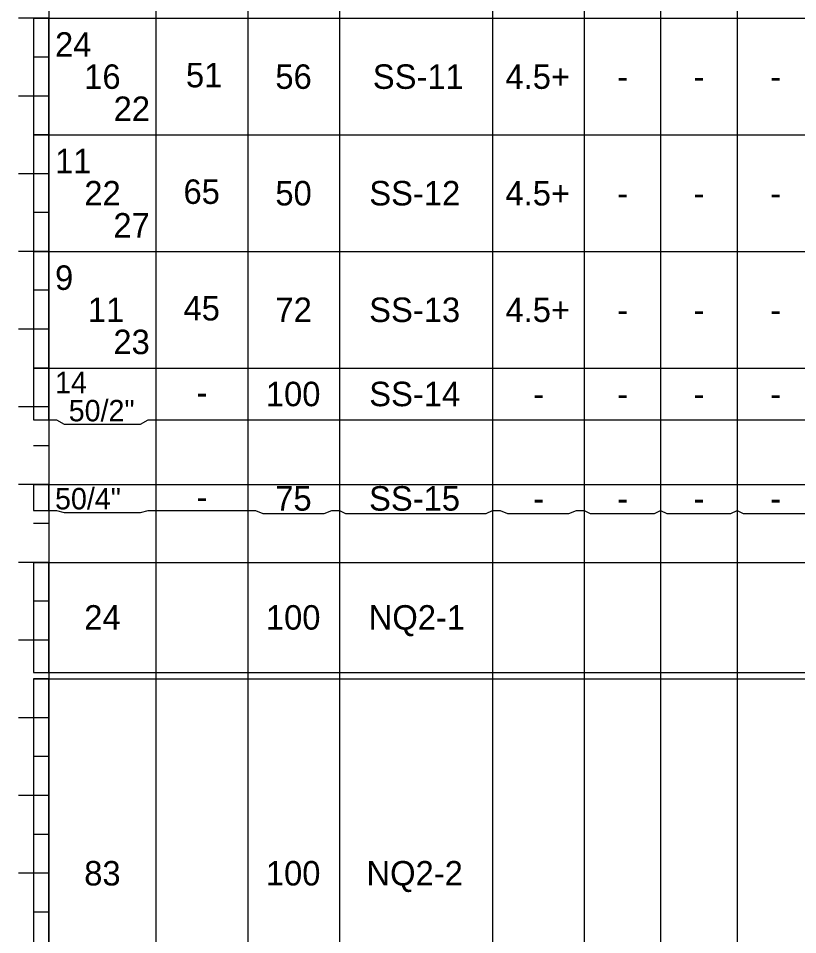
# Model space of a CAD drawing. Extents: x 0 to 0.833, y -0.32 to 0.608.
# Drawn here: x 0.4042 to 0.6165, y -0.0591 to 0.1905 of the extents above; entities that cross this region are included whole.
import ezdxf

# ---------------------------------------------------------------- set-up
doc = ezdxf.new("R2010")
doc.units = 0

msp = doc.modelspace()

# ---------------------------------------------------------------- linework, layer by layer
for points in [[(0.4125, 0.55417), (0.4125, -0.27517)], [(0.4125, 0.55417), (0.4125, -0.27517)], [(0.44167, 0.55417), (0.44167, -0.27517)], [(0.46667, 0.55417), (0.46667, -0.27517)], [(0.49167, 0.55417), (0.49167, -0.27517)], [(0.53333, 0.55417), (0.53333, -0.27517)], [(0.55833, 0.55417), (0.55833, -0.27517)], [(0.57917, 0.54167), (0.57917, -0.27517)], [(0.6, 0.54167), (0.6, -0.27517)], [(0.4125, 0.1905), (0.40417, 0.1905)], [(0.40833, 0.1905), (0.40833, 0.15875)], [(0.40833, 0.1905), (0.4125, 0.1905)], [(0.4125, 0.1905), (0.44167, 0.1905)], [(0.44167, 0.1905), (0.46667, 0.1905)], [(0.46667, 0.1905), (0.49167, 0.1905)], [(0.49167, 0.1905), (0.53333, 0.1905)], [(0.53333, 0.1905), (0.55833, 0.1905)], [(0.55833, 0.1905), (0.57917, 0.1905)], [(0.57917, 0.1905), (0.6, 0.1905)], [(0.6, 0.1905), (0.62083, 0.1905)], [(0.4125, 0.17992), (0.40833, 0.17992)], [(0.4125, 0.16933), (0.40417, 0.16933)], [(0.4125, 0.16933), (0.40833, 0.16933)], [(0.40833, 0.15875), (0.4125, 0.15875)], [(0.40833, 0.15875), (0.40833, 0.127)], [(0.40833, 0.15875), (0.4125, 0.15875)], [(0.4125, 0.15875), (0.40833, 0.15875)], [(0.4125, 0.15875), (0.44167, 0.15875)], [(0.44167, 0.15875), (0.46667, 0.15875)], [(0.46667, 0.15875), (0.49167, 0.15875)], [(0.49167, 0.15875), (0.53333, 0.15875)], [(0.53333, 0.15875), (0.55833, 0.15875)], [(0.55833, 0.15875), (0.57917, 0.15875)], [(0.57917, 0.15875), (0.6, 0.15875)], [(0.6, 0.15875), (0.62083, 0.15875)], [(0.4125, 0.14817), (0.40417, 0.14817)], [(0.4125, 0.14817), (0.40833, 0.14817)], [(0.4125, 0.13758), (0.40833, 0.13758)], [(0.4125, 0.127), (0.40417, 0.127)], [(0.40833, 0.127), (0.4125, 0.127)], [(0.40833, 0.127), (0.40833, 0.09525)], [(0.40833, 0.127), (0.4125, 0.127)], [(0.4125, 0.127), (0.40833, 0.127)], [(0.4125, 0.127), (0.44167, 0.127)], [(0.44167, 0.127), (0.46667, 0.127)], [(0.46667, 0.127), (0.49167, 0.127)], [(0.49167, 0.127), (0.53333, 0.127)], [(0.53333, 0.127), (0.55833, 0.127)], [(0.55833, 0.127), (0.57917, 0.127)], [(0.57917, 0.127), (0.6, 0.127)], [(0.6, 0.127), (0.62083, 0.127)], [(0.4125, 0.11642), (0.40833, 0.11642)], [(0.4125, 0.10583), (0.40417, 0.10583)], [(0.4125, 0.10583), (0.40833, 0.10583)], [(0.40833, 0.09525), (0.4125, 0.09525)], [(0.40833, 0.09525), (0.40833, 0.08114)], [(0.40833, 0.09525), (0.4125, 0.09525)], [(0.4125, 0.09525), (0.40833, 0.09525)], [(0.4125, 0.09525), (0.44167, 0.09525)], [(0.44167, 0.09525), (0.46667, 0.09525)], [(0.46667, 0.09525), (0.49167, 0.09525)], [(0.49167, 0.09525), (0.53333, 0.09525)], [(0.53333, 0.09525), (0.55833, 0.09525)], [(0.55833, 0.09525), (0.57917, 0.09525)], [(0.57917, 0.09525), (0.6, 0.09525)], [(0.6, 0.09525), (0.62083, 0.09525)], [(0.4125, 0.08467), (0.40417, 0.08467)], [(0.4125, 0.08467), (0.40833, 0.08467)], [(0.40833, 0.08114), (0.4125, 0.08114)], [(0.4125, 0.08114), (0.41458, 0.08114), (0.41667, 0.07994), (0.4375, 0.07994), (0.43958, 0.08114), (0.44167, 0.08114)], [(0.44167, 0.08114), (0.46667, 0.08114)], [(0.46667, 0.08114), (0.49167, 0.08114)], [(0.49167, 0.08114), (0.53333, 0.08114)], [(0.53333, 0.08114), (0.55833, 0.08114)], [(0.55833, 0.08114), (0.57917, 0.08114)], [(0.57917, 0.08114), (0.6, 0.08114)], [(0.6, 0.08114), (0.62083, 0.08114)], [(0.4125, 0.07408), (0.40833, 0.07408)], [(0.4125, 0.0635), (0.40417, 0.0635)], [(0.40833, 0.0635), (0.40833, 0.05644)], [(0.40833, 0.0635), (0.4125, 0.0635)], [(0.4125, 0.0635), (0.40833, 0.0635)], [(0.4125, 0.0635), (0.44167, 0.0635)], [(0.44167, 0.0635), (0.46667, 0.0635)], [(0.46667, 0.0635), (0.49167, 0.0635)], [(0.49167, 0.0635), (0.53333, 0.0635)], [(0.53333, 0.0635), (0.55833, 0.0635)], [(0.55833, 0.0635), (0.57917, 0.0635)], [(0.57917, 0.0635), (0.6, 0.0635)], [(0.6, 0.0635), (0.62083, 0.0635)], [(0.40833, 0.05644), (0.4125, 0.05644)], [(0.4125, 0.05644), (0.41458, 0.05644), (0.41667, 0.05595), (0.4375, 0.05595), (0.43958, 0.05644), (0.44167, 0.05644)], [(0.44167, 0.05644), (0.46667, 0.05644)], [(0.46667, 0.05644), (0.46875, 0.05644), (0.47083, 0.05562), (0.4875, 0.05562), (0.48958, 0.05644), (0.49167, 0.05644)], [(0.49167, 0.05644), (0.49333, 0.05562), (0.53167, 0.05562), (0.53333, 0.05644)], [(0.53333, 0.05644), (0.53542, 0.05644), (0.5375, 0.05562), (0.55417, 0.05562), (0.55625, 0.05644), (0.55833, 0.05644)], [(0.55833, 0.05644), (0.56, 0.05562), (0.5775, 0.05562), (0.57917, 0.05644)], [(0.57917, 0.05644), (0.58083, 0.05562), (0.59833, 0.05562), (0.6, 0.05644)], [(0.6, 0.05644), (0.60167, 0.05562), (0.61917, 0.05562), (0.62083, 0.05644)], [(0.4125, 0.05292), (0.40833, 0.05292)], [(0.4125, 0.04233), (0.40417, 0.04233)], [(0.40833, 0.04233), (0.40833, 0.01235)], [(0.40833, 0.04233), (0.4125, 0.04233)], [(0.4125, 0.04233), (0.40833, 0.04233)], [(0.4125, 0.04233), (0.44167, 0.04233)], [(0.44167, 0.04233), (0.46667, 0.04233)], [(0.46667, 0.04233), (0.49167, 0.04233)], [(0.49167, 0.04233), (0.53333, 0.04233)], [(0.53333, 0.04233), (0.55833, 0.04233)], [(0.55833, 0.04233), (0.57917, 0.04233)], [(0.57917, 0.04233), (0.6, 0.04233)], [(0.6, 0.04233), (0.62083, 0.04233)], [(0.4125, 0.03175), (0.40833, 0.03175)], [(0.4125, 0.02117), (0.40417, 0.02117)], [(0.4125, 0.02117), (0.40833, 0.02117)], [(0.40833, 0.01235), (0.4125, 0.01235)], [(0.40833, 0.01058), (0.40833, -0.09525)], [(0.40833, 0.01058), (0.4125, 0.01058)], [(0.4125, 0.01058), (0.40833, 0.01058)], [(0.4125, 0.01235), (0.44167, 0.01235)], [(0.4125, 0.01058), (0.44167, 0.01058)], [(0.44167, 0.01235), (0.46667, 0.01235)], [(0.44167, 0.01058), (0.46667, 0.01058)], [(0.46667, 0.01235), (0.49167, 0.01235)], [(0.46667, 0.01058), (0.49167, 0.01058)], [(0.49167, 0.01235), (0.53333, 0.01235)], [(0.49167, 0.01058), (0.53333, 0.01058)], [(0.53333, 0.01235), (0.55833, 0.01235)], [(0.53333, 0.01058), (0.55833, 0.01058)], [(0.55833, 0.01235), (0.57917, 0.01235)], [(0.55833, 0.01058), (0.57917, 0.01058)], [(0.57917, 0.01235), (0.6, 0.01235)], [(0.57917, 0.01058), (0.6, 0.01058)], [(0.6, 0.01235), (0.62083, 0.01235)], [(0.6, 0.01058), (0.62083, 0.01058)], [(0.4125, 0), (0.40417, 0)], [(0.4125, 0), (0.40833, 0)], [(0.4125, -0.01058), (0.40833, -0.01058)], [(0.4125, -0.02117), (0.40417, -0.02117)], [(0.4125, -0.02117), (0.40833, -0.02117)], [(0.4125, -0.03175), (0.40833, -0.03175)], [(0.4125, -0.04233), (0.40417, -0.04233)], [(0.4125, -0.04233), (0.40833, -0.04233)], [(0.4125, -0.05292), (0.40833, -0.05292)]]:
    msp.add_lwpolyline(points)
for points in [[(0.40833, 0.15875), (0.4125, 0.15875), (0.4125, 0.1905), (0.40833, 0.1905)], [(0.40833, 0.127), (0.4125, 0.127), (0.4125, 0.15875), (0.40833, 0.15875)], [(0.40833, 0.09525), (0.4125, 0.09525), (0.4125, 0.127), (0.40833, 0.127)], [(0.40833, 0.08114), (0.4125, 0.08114), (0.4125, 0.09525), (0.40833, 0.09525)], [(0.40833, 0.05644), (0.4125, 0.05644), (0.4125, 0.0635), (0.40833, 0.0635)], [(0.40833, 0.01235), (0.4125, 0.01235), (0.4125, 0.04233), (0.40833, 0.04233)], [(0.40833, -0.09525), (0.4125, -0.09525), (0.4125, 0.01058), (0.40833, 0.01058)]]:
    msp.add_lwpolyline(points, close=True)

# ---------------------------------------------------------------- texts
for s, height, p in [('24', 0.006667, (0.41417, 0.18004)), ('16', 0.006667, (0.42212, 0.17129)), ('51', 0.006667, (0.44984, 0.17171)), ('56', 0.006667, (0.4742, 0.17129)), ('SS-11', 0.006667, (0.50076, 0.17129)), ('4.5+', 0.006667, (0.5369, 0.17129)), ('-', 0.00667, (0.56734, 0.17129)), ('-', 0.00667, (0.58818, 0.17129)), ('-', 0.00667, (0.60901, 0.17129)), ('22', 0.006667, (0.43014, 0.16254)), ('11', 0.006667, (0.41417, 0.14829)), ('22', 0.006667, (0.42215, 0.13954)), ('65', 0.006667, (0.44917, 0.13996)), ('50', 0.006667, (0.47421, 0.13954)), ('SS-12', 0.006667, (0.4998, 0.13954)), ('4.5+', 0.006667, (0.5369, 0.13954)), ('-', 0.00667, (0.56734, 0.13954)), ('-', 0.00667, (0.58818, 0.13954)), ('-', 0.00667, (0.60901, 0.13954)), ('27', 0.006667, (0.43007, 0.13079)), ('9', 0.00667, (0.41417, 0.11654)), ('45', 0.006667, (0.44917, 0.10821)), ('11', 0.006667, (0.42311, 0.10779)), ('72', 0.006667, (0.47423, 0.10779)), ('SS-13', 0.006667, (0.49977, 0.10779)), ('4.5+', 0.006667, (0.5369, 0.10779)), ('-', 0.00667, (0.56734, 0.10779)), ('-', 0.00667, (0.58818, 0.10779)), ('-', 0.00667, (0.60901, 0.10779)), ('23', 0.006667, (0.43007, 0.09904)), ('14', 0.005833, (0.41417, 0.0884)), ('100', 0.006667, (0.47162, 0.08486)), ('SS-14', 0.006667, (0.49978, 0.08486)), ('-', 0.00667, (0.45276, 0.08528)), ('-', 0.00667, (0.54443, 0.08486)), ('-', 0.00667, (0.56734, 0.08486)), ('-', 0.00667, (0.58818, 0.08486)), ('-', 0.00667, (0.60901, 0.08486)), ('50/2"', 0.005833, (0.4179, 0.08074)), ('50/4"', 0.005833, (0.41417, 0.05676)), ('75', 0.006667, (0.47417, 0.05642)), ('SS-15', 0.006667, (0.49974, 0.05642)), ('-', 0.00667, (0.45276, 0.05683)), ('-', 0.00667, (0.54443, 0.05642)), ('-', 0.00667, (0.56734, 0.05642)), ('-', 0.00667, (0.58818, 0.05642)), ('-', 0.00667, (0.60901, 0.05642)), ('24', 0.006667, (0.42213, 0.02401)), ('100', 0.006667, (0.47162, 0.02401)), ('NQ2-1', 0.006667, (0.49964, 0.02401)), ('83', 0.006667, (0.42212, -0.04567)), ('100', 0.006667, (0.47162, -0.04567)), ('NQ2-2', 0.006667, (0.49903, -0.04567))]:
    msp.add_text(s, height=height).set_placement(p)

doc.saveas('drawing.dxf')
